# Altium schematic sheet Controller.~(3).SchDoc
size A
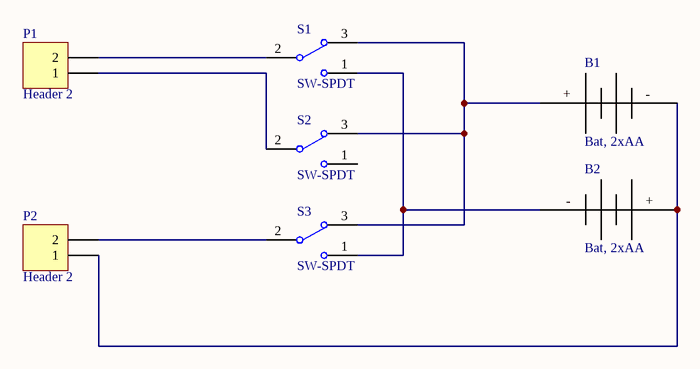
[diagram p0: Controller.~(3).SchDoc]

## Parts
B1  Bat, 2xAA  [Bat1]
B2  Bat, 2xAA  [Bat1]
P1  Header 2  [HDR1X2]
P2  Header 2  [HDR1X2]
S1  SW-SPDT  [TL36WW15050]
S2  SW-SPDT  [TL36WW15050]
S3  SW-SPDT  [TL36WW15050]

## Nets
NetB1_+: B1.+ S1.3 S2.3 S3.3
NetB1_-: B1.- B2.+ P2.1
NetB2_-: B2.- S1.1 S3.1
NetP1_1: P1.1 S2.2
NetP1_2: P1.2 S1.2
NetP2_2: P2.2 S3.2

Not connected (* = marked no-connect by the designer): S2 1

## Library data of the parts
P1 P2 = Header 2: Header, 2-Pin
S1-S3 = SW-SPDT: SPDT Subminiature Toggle Switch, Right Angle Mounting, Vertical Actuation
